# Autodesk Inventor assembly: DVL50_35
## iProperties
Created: 2009-07
Part Number: DVL50_35
Document SubType Name: Assembly
Designer: TB
Mass: 710.42 g
Surface Area: 1534.35 cm^2
Volume: 710.42 cm^3
Density: 1 g/cm^3
Description: KM DVL 50/35 - 100 mm
Slaglengde: 100.000 mm
Author: TB
